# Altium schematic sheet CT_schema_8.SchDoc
size 287 x 160 mm
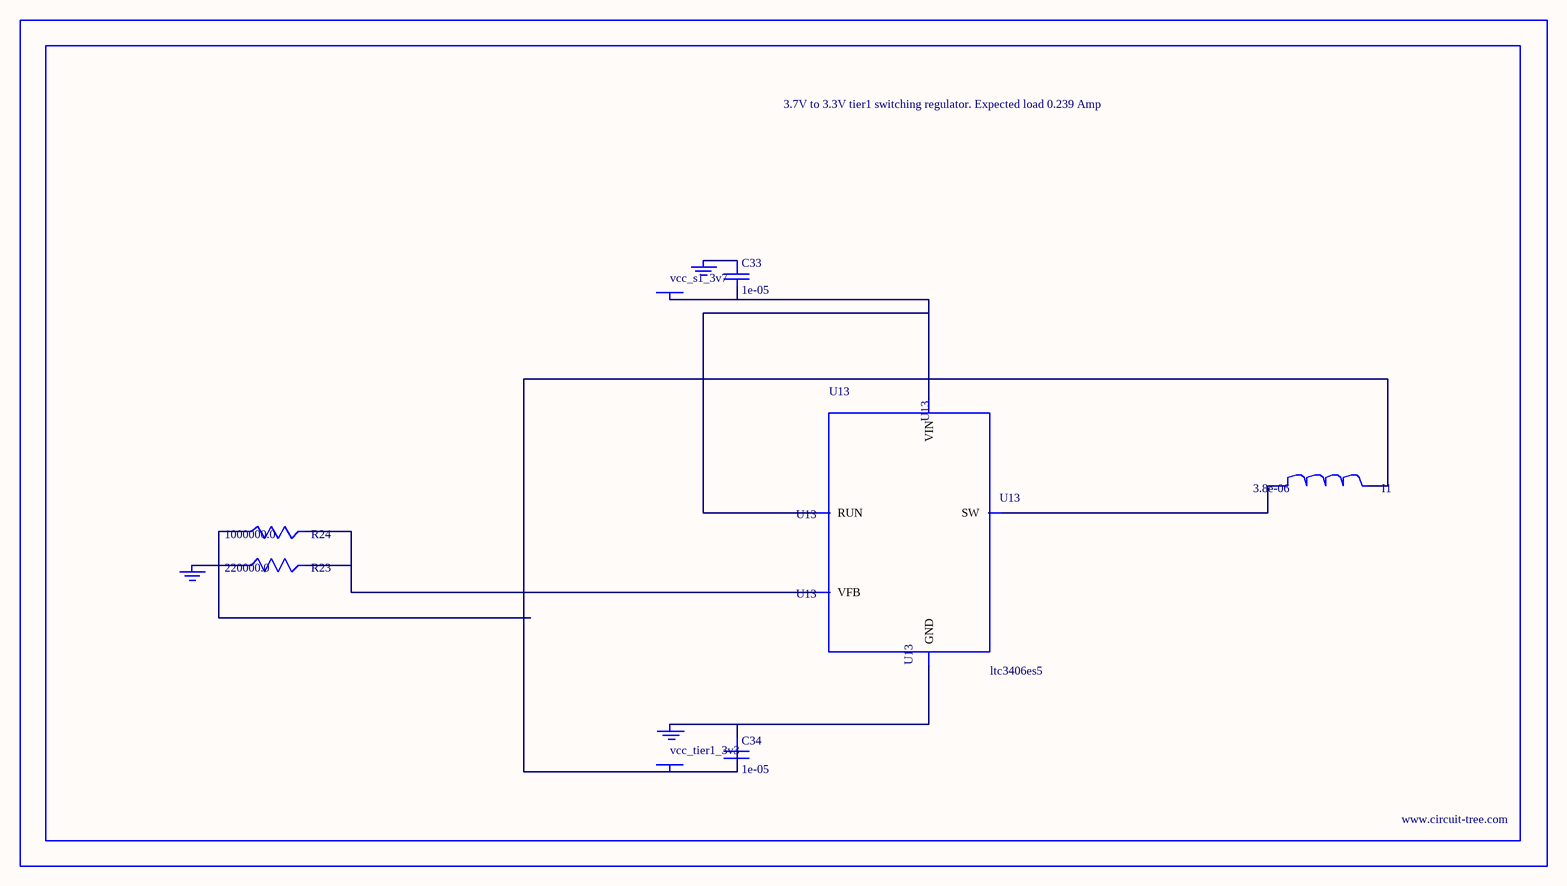
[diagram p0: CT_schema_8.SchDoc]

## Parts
BORDER7  (no value)
C33  1e-05  [C0805]
C34  1e-05  [C0805]
GND_INSTANCE_7_0  (no value)
GND_INSTANCE_7_1  (no value)
GND_INSTANCE_7_2  (no value)
I1  3.8e-06  [DR1040]
POWER_INSTANCE_7_0  vcc_tier1_3v3
POWER_INSTANCE_7_1  vcc_s1_3v7
R23  220000.0  [R0603]
R24  1000000.0  [R0603]
U13  ltc3406es5  [TSOT-23-5]

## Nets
NetC33_1: C33.1 GND_INSTANCE_7_1.0(GND)
NetC33_2: C33.2 POWER_INSTANCE_7_1.0(PWR) U13.1(RUN) U13.4(VIN)
NetC34_1: C34.1 GND_INSTANCE_7_0.0(GND) U13.2(GND)
NetC34_2: C34.2 I1.2 POWER_INSTANCE_7_0.0(PWR) R24.1
NetGND_INSTANCE_7_2_0: GND_INSTANCE_7_2.0(GND) R23.1
NetI1_1: I1.1 U13.3(SW)
NetR23_2: R23.2 R24.2 U13.5(VFB)

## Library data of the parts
BORDER7 = BORDER_PAGE7
C33 C34 = C0805C106K8RACTU
GND_INSTANCE_7_0-GND_INSTANCE_7_2 = GND
I1 = DR1040-3R8-R
POWER_INSTANCE_7_0 POWER_INSTANCE_7_1 = PWR
R23 = RC0603JR-07220KL
R24 = RC0603JR-071ML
